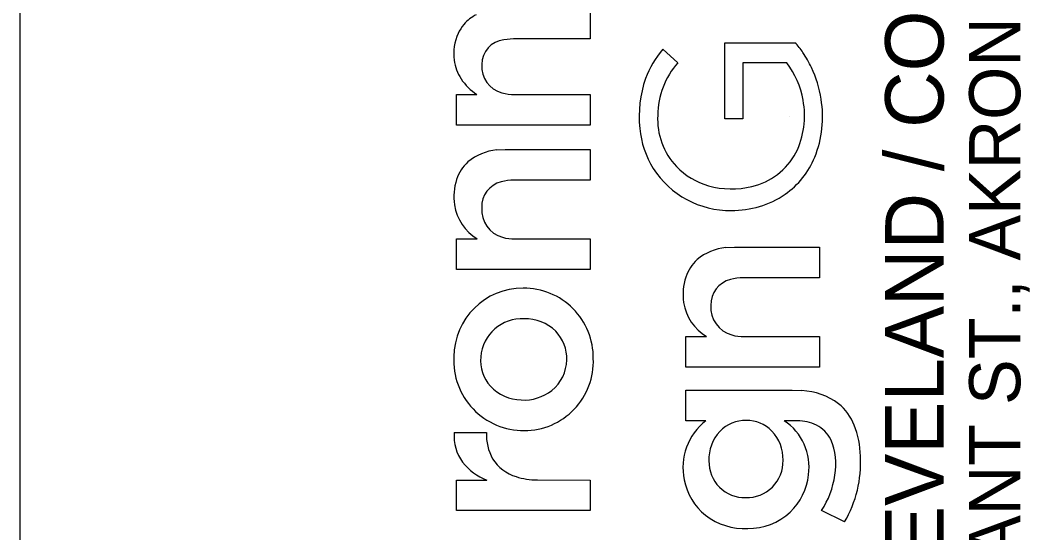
# Model space of a CAD drawing. Extents: x 117359.7 to 117393.7, y 12355.1 to 12408.1.
# Drawn here: x 117391.708 to 117392.693, y 12389.157 to 12389.656 of the extents above; entities that cross this region are included whole.
import ezdxf

# ---------------------------------------------------------------- set-up
doc = ezdxf.new("R2010")
doc.units = 0
doc.layers.add('SH_Border', color=7, linetype='Continuous')
doc.layers.add('SH_Data', color=7, linetype='Continuous')

msp = doc.modelspace()

# ---------------------------------------------------------------- linework, layer by layer
at = {"layer": 'SH_Border'}
msp.add_line((117391.70841, 12386.56248), (117391.70841, 12407.56248), dxfattribs=at)
at = {"layer": 'SH_Data'}
for p, q in [((117392.26412, 12389.66796), (117392.26412, 12389.63816)), ((117392.1893, 12389.63815), (117392.17984, 12389.63722)), ((117392.26412, 12389.63816), (117392.1893, 12389.63815)), ((117392.39521, 12389.63433), (117392.46356, 12389.6344)), ((117392.39521, 12389.56026), (117392.39521, 12389.63433)), ((117392.33477, 12389.62797), (117392.34955, 12389.61489)), ((117392.41289, 12389.61489), (117392.41273, 12389.56024)), ((117392.45577, 12389.61475), (117392.41289, 12389.61489)), ((117392.13383, 12389.554), (117392.13385, 12389.58386)), ((117392.13385, 12389.58386), (117392.15356, 12389.58386)), ((117392.19047, 12389.58386), (117392.26412, 12389.58384)), ((117392.26412, 12389.58384), (117392.26412, 12389.55404)), ((117392.45841, 12389.56248), (117392.45841, 12389.56248)), ((117392.26412, 12389.55404), (117392.13383, 12389.554)), ((117392.41273, 12389.56024), (117392.39521, 12389.56026)), ((117392.17279, 12389.52984), (117392.1813, 12389.53031)), ((117392.1813, 12389.53031), (117392.26412, 12389.53031)), ((117392.26412, 12389.53031), (117392.26412, 12389.50052)), ((117392.26412, 12389.50052), (117392.1898, 12389.50044)), ((117392.13383, 12389.44314), (117392.15393, 12389.44319)), ((117392.13383, 12389.41334), (117392.13383, 12389.44314)), ((117392.19063, 12389.44319), (117392.2641, 12389.44319)), ((117392.2641, 12389.44319), (117392.26412, 12389.41344)), ((117392.39625, 12389.43468), (117392.40475, 12389.43514)), ((117392.40475, 12389.43514), (117392.48757, 12389.43514)), ((117392.48757, 12389.43514), (117392.48757, 12389.40535)), ((117392.26412, 12389.41344), (117392.13383, 12389.41334)), ((117392.48757, 12389.40535), (117392.41326, 12389.40528)), ((117392.35728, 12389.34798), (117392.37738, 12389.34803)), ((117392.35728, 12389.31817), (117392.35728, 12389.34798)), ((117392.41408, 12389.34803), (117392.48755, 12389.34803)), ((117392.48755, 12389.34803), (117392.48757, 12389.31827)), ((117392.48757, 12389.31827), (117392.35728, 12389.31817)), ((117392.3573, 12389.26584), (117392.3573, 12389.29571)), ((117392.3573, 12389.29571), (117392.46077, 12389.29571)), ((117392.46077, 12389.29571), (117392.47032, 12389.29533)), ((117392.37677, 12389.26584), (117392.3573, 12389.26584)), ((117392.46603, 12389.26604), (117392.45328, 12389.26609)), ((117392.1314, 12389.25441), (117392.16295, 12389.25441)), ((117392.13383, 12389.20826), (117392.16314, 12389.20827)), ((117392.13383, 12389.17841), (117392.13383, 12389.20826)), ((117392.21253, 12389.20829), (117392.26412, 12389.20821)), ((117392.26412, 12389.20821), (117392.26406, 12389.17841)), ((117392.26406, 12389.17841), (117392.13383, 12389.17841)), ((117392.512, 12389.16739), (117392.48961, 12389.17846))]:
    msp.add_line(p, q, dxfattribs=at)
for points in [[(117392.19059, 12389.66801), (117392.26412, 12389.66796), (117392.26412, 12389.63816), (117392.1893, 12389.63815), (117392.17984, 12389.63722)], [(117392.45577, 12389.61475), (117392.41289, 12389.61489), (117392.41273, 12389.56024), (117392.39521, 12389.56026), (117392.39521, 12389.63433), (117392.46356, 12389.6344)], [(117392.33477, 12389.62797), (117392.34955, 12389.61489)], [(117392.13383, 12389.554), (117392.13385, 12389.58386), (117392.15356, 12389.58386)], [(117392.19047, 12389.58386), (117392.26412, 12389.58384), (117392.26412, 12389.55404), (117392.13383, 12389.554)], [(117392.17279, 12389.52984), (117392.1813, 12389.53031), (117392.26412, 12389.53031), (117392.26412, 12389.50052), (117392.1898, 12389.50044)], [(117392.13383, 12389.41334), (117392.13383, 12389.44314), (117392.15393, 12389.44319)], [(117392.19063, 12389.44319), (117392.2641, 12389.44319), (117392.26412, 12389.41344), (117392.13383, 12389.41334)], [(117392.39625, 12389.43468), (117392.40475, 12389.43514), (117392.48757, 12389.43514), (117392.48757, 12389.40535), (117392.41326, 12389.40528)], [(117392.35728, 12389.31817), (117392.35728, 12389.34798), (117392.37738, 12389.34803)], [(117392.41408, 12389.34803), (117392.48755, 12389.34803), (117392.48757, 12389.31827), (117392.35728, 12389.31817)], [(117392.37677, 12389.26584), (117392.3573, 12389.26584), (117392.3573, 12389.29571), (117392.46077, 12389.29571), (117392.47032, 12389.29533)], [(117392.46603, 12389.26604), (117392.45328, 12389.26609)], [(117392.1314, 12389.25441), (117392.16295, 12389.25441)], [(117392.21253, 12389.20829), (117392.26412, 12389.20821), (117392.26406, 12389.17841), (117392.13383, 12389.17841)], [(117392.13383, 12389.17841), (117392.13383, 12389.20826), (117392.16314, 12389.20827)], [(117392.512, 12389.16739), (117392.48961, 12389.17846)]]:
    msp.add_lwpolyline(points, dxfattribs=at)
for centre, radius, start, end in [((117392.1722, 12389.62515), 0.04137, 117.91625, 139.24296), ((117392.1722, 12389.62515), 0.04137, 117.91625, 139.24296), ((117392.17035, 12389.627), 0.03875, 139.52447, 154.84698), ((117392.17035, 12389.627), 0.03875, 139.52447, 154.84698), ((117392.17985, 12389.62368), 0.04877, 156.06382, 187.3493), ((117392.17985, 12389.62368), 0.04877, 156.06382, 187.3493), ((117392.18262, 12389.61304), 0.02434, 96.5532, 179.94902), ((117392.18262, 12389.61304), 0.02434, 96.5532, 179.94902), ((117392.43339, 12389.60185), 0.04438, 30.98913, 47.16099), ((117392.43339, 12389.60185), 0.04438, 30.98913, 47.16099), ((117392.41004, 12389.56435), 0.09855, 139.79476, 159.13696), ((117392.41004, 12389.56435), 0.09855, 139.79476, 159.13696), ((117392.37932, 12389.56266), 0.11106, 25.30315, 33.96179), ((117392.37932, 12389.56266), 0.11106, 25.30315, 33.96179), ((117392.17302, 12389.62222), 0.04181, 186.5579, 213.38846), ((117392.17302, 12389.62222), 0.04181, 186.5579, 213.38846), ((117392.18449, 12389.61111), 0.02628, 175.722, 255.78627), ((117392.18449, 12389.61111), 0.02628, 175.722, 255.78627), ((117392.4074, 12389.56328), 0.07753, 138.25804, 179.70064), ((117392.4074, 12389.56328), 0.07753, 138.25804, 179.70064), ((117392.38729, 12389.56347), 0.08556, 10.07509, 36.83189), ((117392.38729, 12389.56347), 0.08556, 10.07509, 36.83189), ((117392.3788, 12389.56235), 0.11166, 8.80339, 25.33484), ((117392.3788, 12389.56235), 0.11166, 8.80339, 25.33484), ((117392.18727, 12389.63326), 0.0598, 214.70433, 235.68724), ((117392.18727, 12389.63326), 0.0598, 214.70433, 235.68724), ((117392.42711, 12389.56216), 0.11536, 161.14379, 185.62812), ((117392.42711, 12389.56216), 0.11536, 161.14379, 185.62812), ((117392.19035, 12389.62766), 0.0438, 253.66719, 270.14979), ((117392.19035, 12389.62766), 0.0438, 253.66719, 270.14979), ((117392.39265, 12389.56305), 0.08036, 333.46689, 11.03668), ((117392.39265, 12389.56305), 0.08036, 333.46689, 11.03668), ((117392.38405, 12389.56225), 0.10649, 338.28866, 9.28548), ((117392.38405, 12389.56225), 0.10649, 338.28866, 9.28548), ((117392.39652, 12389.5598), 0.06676, 176.66577, 223.6912), ((117392.39652, 12389.5598), 0.06676, 176.66577, 223.6912), ((117392.40176, 12389.55947), 0.08987, 185.50773, 212.01294), ((117392.40176, 12389.55947), 0.08987, 185.50773, 212.01294), ((117392.17712, 12389.48015), 0.04988, 94.97056, 130.22484), ((117392.17712, 12389.48015), 0.04988, 94.97056, 130.22484), ((117392.40708, 12389.55795), 0.0652, 282.88151, 331.81475), ((117392.40708, 12389.55795), 0.0652, 282.88151, 331.81475), ((117392.40676, 12389.55416), 0.08241, 305.03061, 337.67573), ((117392.40676, 12389.55416), 0.08241, 305.03061, 337.67573), ((117392.17189, 12389.4885), 0.04016, 132.22383, 161.68229), ((117392.17189, 12389.4885), 0.04016, 132.22383, 161.68229), ((117392.39886, 12389.56259), 0.07039, 224.02147, 253.88), ((117392.39886, 12389.56259), 0.07039, 224.02147, 253.88), ((117392.40052, 12389.55996), 0.08908, 212.70222, 270.71399), ((117392.40052, 12389.55996), 0.08908, 212.70222, 270.71399), ((117392.18713, 12389.48406), 0.05602, 162.27398, 187.79173), ((117392.18713, 12389.48406), 0.05602, 162.27398, 187.79173), ((117392.18323, 12389.47454), 0.02498, 103.68683, 182.21395), ((117392.18323, 12389.47454), 0.02498, 103.68683, 182.21395), ((117392.18948, 12389.45444), 0.04601, 89.60515, 105.33026), ((117392.18948, 12389.45444), 0.04601, 89.60515, 105.33026), ((117392.40159, 12389.57502), 0.08309, 254.45353, 283.9512), ((117392.40159, 12389.57502), 0.08309, 254.45353, 283.9512), ((117392.4027, 12389.56227), 0.09138, 269.3273, 304.19632), ((117392.4027, 12389.56227), 0.09138, 269.3273, 304.19632), ((117392.17867, 12389.48389), 0.04763, 188.96462, 238.69865), ((117392.17867, 12389.48389), 0.04763, 188.96462, 238.69865), ((117392.18576, 12389.47145), 0.02757, 175.58441, 255.13816), ((117392.18576, 12389.47145), 0.02757, 175.58441, 255.13816), ((117392.19024, 12389.48534), 0.04215, 254.08913, 270.52838), ((117392.19024, 12389.48534), 0.04215, 254.08913, 270.52838), ((117392.40057, 12389.38499), 0.04988, 94.97056, 130.22484), ((117392.40057, 12389.38499), 0.04988, 94.97056, 130.22484), ((117392.39535, 12389.39333), 0.04016, 132.22383, 161.68229), ((117392.39535, 12389.39333), 0.04016, 132.22383, 161.68229), ((117392.41058, 12389.3889), 0.05602, 162.27398, 187.79173), ((117392.41058, 12389.3889), 0.05602, 162.27398, 187.79173), ((117392.41294, 12389.35927), 0.04601, 89.60515, 105.33026), ((117392.41294, 12389.35927), 0.04601, 89.60515, 105.33026), ((117392.19855, 12389.32791), 0.0674, 89.84756, 179.64047), ((117392.19855, 12389.32791), 0.0674, 89.84756, 179.64047), ((117392.19898, 12389.32722), 0.0681, 359.54009, 90.21138), ((117392.19898, 12389.32722), 0.0681, 359.54009, 90.21138), ((117392.40669, 12389.37937), 0.02498, 103.68683, 182.21395), ((117392.40669, 12389.37937), 0.02498, 103.68683, 182.21395), ((117392.40213, 12389.38872), 0.04763, 188.96462, 238.69865), ((117392.40213, 12389.38872), 0.04763, 188.96462, 238.69865), ((117392.40921, 12389.37629), 0.02757, 175.58441, 255.13816), ((117392.40921, 12389.37629), 0.02757, 175.58441, 255.13816), ((117392.19763, 12389.32511), 0.0404, 87.04809, 175.57259), ((117392.19763, 12389.32511), 0.0404, 87.04809, 175.57259), ((117392.20045, 12389.32247), 0.04299, 45.84264, 90.98008), ((117392.20045, 12389.32247), 0.04299, 45.84264, 90.98008), ((117392.20298, 12389.32669), 0.03821, 357.88569, 44.15902), ((117392.20298, 12389.32669), 0.03821, 357.88569, 44.15902), ((117392.41369, 12389.39017), 0.04215, 254.08913, 270.52838), ((117392.41369, 12389.39017), 0.04215, 254.08913, 270.52838), ((117392.19923, 12389.32457), 0.06819, 176.8344, 270.40384), ((117392.19923, 12389.32457), 0.06819, 176.8344, 270.40384), ((117392.1957, 12389.32498), 0.03848, 175.15378, 221.14706), ((117392.1957, 12389.32498), 0.03848, 175.15378, 221.14706), ((117392.19964, 12389.32387), 0.06749, 270.06243, 2.37759), ((117392.19964, 12389.32387), 0.06749, 270.06243, 2.37759), ((117392.20287, 12389.32566), 0.0383, 308.28936, 359.43468), ((117392.20287, 12389.32566), 0.0383, 308.28936, 359.43468), ((117392.19759, 12389.32855), 0.04228, 223.09994, 268.80895), ((117392.19759, 12389.32855), 0.04228, 223.09994, 268.80895), ((117392.19936, 12389.33038), 0.04418, 266.56515, 308.06078), ((117392.19936, 12389.33038), 0.04418, 266.56515, 308.06078), ((117392.46747, 12389.23037), 0.06503, 53.40344, 87.49062), ((117392.46747, 12389.23037), 0.06503, 53.40344, 87.49062), ((117392.47358, 12389.24287), 0.05141, 21.60748, 50.5577), ((117392.47358, 12389.24287), 0.05141, 21.60748, 50.5577), ((117392.41534, 12389.23175), 0.0346, 88.47302, 136.42562), ((117392.41534, 12389.23175), 0.0346, 88.47302, 136.42562), ((117392.41654, 12389.23211), 0.03424, 44.27195, 90.47623), ((117392.41654, 12389.23211), 0.03424, 44.27195, 90.47623), ((117392.41132, 12389.22061), 0.05692, 127.37482, 192.22468), ((117392.41132, 12389.22061), 0.05692, 127.37482, 192.22468), ((117392.42261, 12389.22077), 0.05472, 352.1125, 55.92295), ((117392.42261, 12389.22077), 0.05472, 352.1125, 55.92295), ((117392.46506, 12389.21973), 0.04633, 65.01687, 88.8011), ((117392.46506, 12389.21973), 0.04633, 65.01687, 88.8011), ((117392.47101, 12389.23403), 0.03085, 26.26808, 63.80301), ((117392.47101, 12389.23403), 0.03085, 26.26808, 63.80301), ((117392.4391, 12389.22962), 0.08835, 1.15143, 21.3627), ((117392.4391, 12389.22962), 0.08835, 1.15143, 21.3627), ((117392.17457, 12389.2513), 0.04329, 175.87313, 216.34747), ((117392.17457, 12389.2513), 0.04329, 175.87313, 216.34747), ((117392.20927, 12389.25196), 0.04639, 176.9688, 209.60636), ((117392.20927, 12389.25196), 0.04639, 176.9688, 209.60636), ((117392.41982, 12389.2285), 0.0401, 137.46739, 182.33237), ((117392.41982, 12389.2285), 0.0401, 137.46739, 182.33237), ((117392.41209, 12389.22848), 0.03996, 358.57141, 43.53765), ((117392.41209, 12389.22848), 0.03996, 358.57141, 43.53765), ((117392.44406, 12389.22402), 0.05953, 349.30734, 23.43071), ((117392.44406, 12389.22402), 0.05953, 349.30734, 23.43071), ((117392.20355, 12389.25062), 0.04079, 211.94466, 253.2028), ((117392.20355, 12389.25062), 0.04079, 211.94466, 253.2028), ((117392.41659, 12389.22652), 0.03546, 268.27882, 1.55016), ((117392.41659, 12389.22652), 0.03546, 268.27882, 1.55016), ((117392.41378, 12389.22492), 0.11383, 329.6388, 3.25998), ((117392.41378, 12389.22492), 0.11383, 329.6388, 3.25998), ((117392.18307, 12389.25964), 0.05511, 218.09809, 248.7907), ((117392.18307, 12389.25964), 0.05511, 218.09809, 248.7907), ((117392.41486, 12389.22618), 0.03511, 178.88208, 271.08374), ((117392.41486, 12389.22618), 0.03511, 178.88208, 271.08374), ((117392.21306, 12389.27898), 0.07069, 252.46555, 269.57296), ((117392.21306, 12389.27898), 0.07069, 252.46555, 269.57296), ((117392.41304, 12389.21944), 0.05837, 190.75182, 231.28919), ((117392.41304, 12389.21944), 0.05837, 190.75182, 231.28919), ((117392.41828, 12389.21956), 0.05887, 313.74196, 353.8554), ((117392.41828, 12389.21956), 0.05887, 313.74196, 353.8554), ((117392.41579, 12389.22582), 0.08771, 327.31495, 351.57478), ((117392.41579, 12389.22582), 0.08771, 327.31495, 351.57478), ((117392.41473, 12389.22361), 0.06269, 232.46061, 272.59022), ((117392.41473, 12389.22361), 0.06269, 232.46061, 272.59022), ((117392.41795, 12389.22149), 0.06051, 269.6361, 312.70877), ((117392.41795, 12389.22149), 0.06051, 269.6361, 312.70877)]:
    msp.add_arc(centre, radius, start, end, dxfattribs=at)

# ---------------------------------------------------------------- texts
for s, height, p in [('450 GRANT ST., AKRON, OH  44311', 0.0498462, (117392.68329, 12388.89986)), ('AKRON / CLEVELAND / COLUMBUS', 0.056969, (117392.60853, 12388.70048))]:
    msp.add_text(s, height=height, rotation=90, dxfattribs=at).set_placement(p)

doc.saveas('drawing.dxf')
